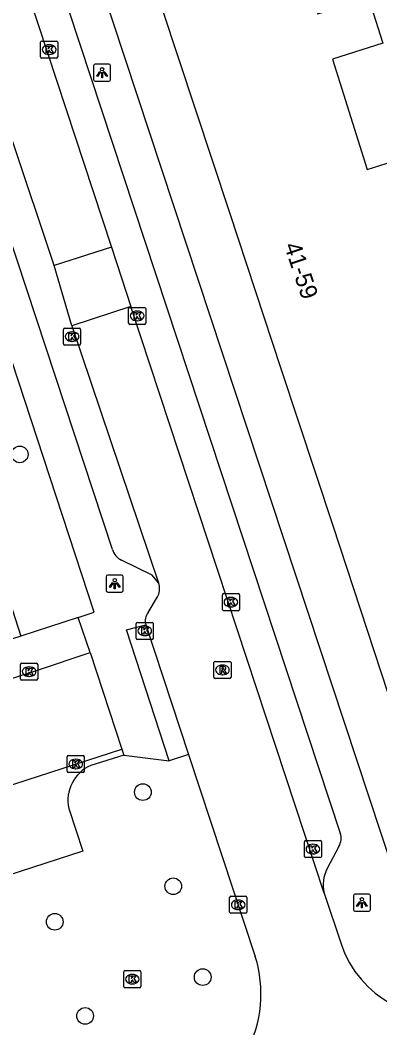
# Model space of a CAD drawing. Extents: x 159377 to 159983, y 382996 to 383595.
# Drawn here: x 159571.9 to 159592.9, y 383285.7 to 383344.8 of the extents above; entities that cross this region are included whole.
import ezdxf

# ---------------------------------------------------------------- set-up
doc = ezdxf.new("R2010")
doc.units = 0
for name, color, linetype in [('IMGEO_Boom', 7, 'Continuous'), ('IMGEO_Kolk', 7, 'Continuous'), ('IMGEO_Lichtpunt', 7, 'Continuous'), ('IMGEO_Pand', 7, 'Continuous'), ('IMGEO_Pand_nummerreeks', 7, 'Continuous'), ('IMGEO_Rijbaan_lokaal_open', 7, 'Continuous'), ('IMGEO_Rioolput', 7, 'Continuous'), ('IMGEO_Voetpad_open', 7, 'Continuous')]:
    doc.layers.add(name, color=color, linetype=linetype)

msp = doc.modelspace()

# ---------------------------------------------------------------- linework, layer by layer
at = {"layer": 'IMGEO_Boom'}
for centre in [(159571.842, 383319.363), (159579.055, 383299.558), (159580.837, 383294.038), (159573.891, 383291.953), (159582.558, 383288.709), (159575.673, 383286.434)]:
    msp.add_circle(centre, 0.489, dxfattribs=at)
at = {"layer": 'IMGEO_Kolk'}
for p, q in [((159573.064, 383342.675), (159573.064, 383343.527)), ((159573.139, 383343.601), (159573.991, 383343.601)), ((159574.065, 383343.527), (159574.065, 383342.675)), ((159573.552, 383343.381), (159573.577, 383343.381)), ((159573.991, 383342.601), (159573.139, 383342.601)), ((159573.575, 383342.821), (159573.55, 383342.821)), ((159578.219, 383327.058), (159578.219, 383327.91)), ((159578.294, 383327.984), (159579.146, 383327.984)), ((159578.707, 383327.764), (159578.732, 383327.764)), ((159579.22, 383327.91), (159579.22, 383327.058)), ((159579.146, 383326.984), (159578.294, 383326.984)), ((159578.73, 383327.204), (159578.705, 383327.204)), ((159574.405, 383325.842), (159574.405, 383326.694)), ((159574.48, 383326.768), (159575.332, 383326.768)), ((159574.893, 383326.548), (159574.918, 383326.548)), ((159575.406, 383326.694), (159575.406, 383325.842)), ((159575.332, 383325.768), (159574.48, 383325.768)), ((159574.916, 383325.988), (159574.891, 383325.988)), ((159583.712, 383310.272), (159583.712, 383311.124)), ((159583.787, 383311.198), (159584.639, 383311.198)), ((159584.2, 383310.978), (159584.225, 383310.978)), ((159584.713, 383311.124), (159584.713, 383310.272)), ((159584.223, 383310.418), (159584.198, 383310.418)), ((159584.639, 383310.198), (159583.787, 383310.198)), ((159578.666, 383308.588), (159578.666, 383309.44)), ((159578.741, 383309.514), (159579.593, 383309.514)), ((159579.154, 383309.294), (159579.179, 383309.294)), ((159579.667, 383309.44), (159579.667, 383308.588)), ((159579.177, 383308.734), (159579.152, 383308.734)), ((159579.593, 383308.514), (159578.741, 383308.514)), ((159571.891, 383306.197), (159571.891, 383307.049)), ((159571.966, 383307.123), (159572.818, 383307.123)), ((159572.379, 383306.903), (159572.404, 383306.903)), ((159572.892, 383307.049), (159572.892, 383306.197)), ((159572.402, 383306.343), (159572.377, 383306.343)), ((159572.818, 383306.123), (159571.966, 383306.123)), ((159574.624, 383300.779), (159574.624, 383301.631)), ((159574.699, 383301.705), (159575.551, 383301.705)), ((159575.625, 383301.631), (159575.625, 383300.779)), ((159575.135, 383300.925), (159575.11, 383300.925)), ((159575.112, 383301.485), (159575.137, 383301.485)), ((159575.551, 383300.705), (159574.699, 383300.705)), ((159588.514, 383295.791), (159588.514, 383296.643)), ((159588.589, 383296.717), (159589.441, 383296.717)), ((159589.002, 383296.497), (159589.027, 383296.497)), ((159589.515, 383296.643), (159589.515, 383295.791)), ((159589.441, 383295.717), (159588.589, 383295.717)), ((159589.025, 383295.937), (159589, 383295.937)), ((159584.137, 383292.525), (159584.137, 383293.377)), ((159584.212, 383293.451), (159585.064, 383293.451)), ((159584.625, 383293.231), (159584.65, 383293.231)), ((159585.138, 383293.377), (159585.138, 383292.525)), ((159584.648, 383292.671), (159584.623, 383292.671)), ((159585.064, 383292.451), (159584.212, 383292.451)), ((159578.01, 383289.089), (159578.862, 383289.089)), ((159577.935, 383288.163), (159577.935, 383289.015)), ((159578.423, 383288.869), (159578.448, 383288.869)), ((159578.936, 383289.015), (159578.936, 383288.163)), ((159578.862, 383288.089), (159578.01, 383288.089)), ((159578.446, 383288.309), (159578.421, 383288.309))]:
    msp.add_line(p, q, dxfattribs=at)
for points in [[(159573.064, 383342.675), (159573.064, 383343.527)], [(159573.139, 383343.601), (159573.991, 383343.601)], [(159574.065, 383343.527), (159574.065, 383342.675)], [(159573.385, 383343.301), (159573.508, 383343.301), (159573.508, 383343.15), (159573.638, 383343.301), (159573.802, 383343.301), (159573.656, 383343.15), (159573.809, 383342.901), (159573.657, 383342.901), (159573.572, 383343.065), (159573.508, 383342.998), (159573.508, 383342.901), (159573.385, 383342.901), (159573.385, 383343.301)], [(159573.991, 383342.601), (159573.139, 383342.601)], [(159578.219, 383327.058), (159578.219, 383327.91)], [(159578.294, 383327.984), (159579.146, 383327.984)], [(159578.54, 383327.684), (159578.663, 383327.684), (159578.663, 383327.533), (159578.793, 383327.684), (159578.957, 383327.684), (159578.811, 383327.533), (159578.964, 383327.284), (159578.812, 383327.284), (159578.727, 383327.448), (159578.663, 383327.381), (159578.663, 383327.284), (159578.54, 383327.284), (159578.54, 383327.684)], [(159579.22, 383327.91), (159579.22, 383327.058)], [(159579.146, 383326.984), (159578.294, 383326.984)], [(159574.405, 383325.842), (159574.405, 383326.694)], [(159574.48, 383326.768), (159575.332, 383326.768)], [(159574.726, 383326.468), (159574.849, 383326.468), (159574.849, 383326.317), (159574.979, 383326.468), (159575.143, 383326.468), (159574.997, 383326.317), (159575.15, 383326.068), (159574.998, 383326.068), (159574.913, 383326.232), (159574.849, 383326.165), (159574.849, 383326.068), (159574.726, 383326.068), (159574.726, 383326.468)], [(159575.406, 383326.694), (159575.406, 383325.842)], [(159575.332, 383325.768), (159574.48, 383325.768)], [(159583.712, 383310.272), (159583.712, 383311.124)], [(159583.787, 383311.198), (159584.639, 383311.198)], [(159584.713, 383311.124), (159584.713, 383310.272)], [(159584.033, 383310.898), (159584.156, 383310.898), (159584.156, 383310.747), (159584.286, 383310.898), (159584.45, 383310.898), (159584.304, 383310.747), (159584.457, 383310.498), (159584.305, 383310.498), (159584.22, 383310.662), (159584.156, 383310.595), (159584.156, 383310.498), (159584.033, 383310.498), (159584.033, 383310.898)], [(159584.639, 383310.198), (159583.787, 383310.198)], [(159578.666, 383308.588), (159578.666, 383309.44)], [(159578.741, 383309.514), (159579.593, 383309.514)], [(159578.987, 383309.214), (159579.11, 383309.214), (159579.11, 383309.063), (159579.24, 383309.214), (159579.404, 383309.214), (159579.258, 383309.063), (159579.411, 383308.814), (159579.259, 383308.814), (159579.174, 383308.978), (159579.11, 383308.911), (159579.11, 383308.814), (159578.987, 383308.814), (159578.987, 383309.214)], [(159579.667, 383309.44), (159579.667, 383308.588)], [(159579.593, 383308.514), (159578.741, 383308.514)], [(159571.891, 383306.197), (159571.891, 383307.049)], [(159571.966, 383307.123), (159572.818, 383307.123)], [(159572.212, 383306.823), (159572.335, 383306.823), (159572.335, 383306.672), (159572.465, 383306.823), (159572.629, 383306.823), (159572.483, 383306.672), (159572.636, 383306.423), (159572.484, 383306.423), (159572.399, 383306.587), (159572.335, 383306.52), (159572.335, 383306.423), (159572.212, 383306.423), (159572.212, 383306.823)], [(159572.892, 383307.049), (159572.892, 383306.197)], [(159572.818, 383306.123), (159571.966, 383306.123)], [(159574.624, 383300.779), (159574.624, 383301.631)], [(159574.699, 383301.705), (159575.551, 383301.705)], [(159575.625, 383301.631), (159575.625, 383300.779)], [(159574.945, 383301.405), (159575.068, 383301.405), (159575.068, 383301.254), (159575.198, 383301.405), (159575.362, 383301.405), (159575.216, 383301.254), (159575.369, 383301.005), (159575.217, 383301.005), (159575.132, 383301.169), (159575.068, 383301.102), (159575.068, 383301.005), (159574.945, 383301.005), (159574.945, 383301.405)], [(159575.551, 383300.705), (159574.699, 383300.705)], [(159588.514, 383295.791), (159588.514, 383296.643)], [(159588.589, 383296.717), (159589.441, 383296.717)], [(159588.835, 383296.417), (159588.958, 383296.417), (159588.958, 383296.266), (159589.088, 383296.417), (159589.252, 383296.417), (159589.106, 383296.266), (159589.259, 383296.017), (159589.107, 383296.017), (159589.022, 383296.181), (159588.958, 383296.114), (159588.958, 383296.017), (159588.835, 383296.017), (159588.835, 383296.417)], [(159589.515, 383296.643), (159589.515, 383295.791)], [(159589.441, 383295.717), (159588.589, 383295.717)], [(159584.137, 383292.525), (159584.137, 383293.377)], [(159584.212, 383293.451), (159585.064, 383293.451)], [(159585.138, 383293.377), (159585.138, 383292.525)], [(159584.458, 383293.151), (159584.581, 383293.151), (159584.581, 383293), (159584.711, 383293.151), (159584.875, 383293.151), (159584.729, 383293), (159584.882, 383292.751), (159584.73, 383292.751), (159584.645, 383292.915), (159584.581, 383292.848), (159584.581, 383292.751), (159584.458, 383292.751), (159584.458, 383293.151)], [(159585.064, 383292.451), (159584.212, 383292.451)], [(159578.01, 383289.089), (159578.862, 383289.089)], [(159577.935, 383288.163), (159577.935, 383289.015)], [(159578.256, 383288.789), (159578.379, 383288.789), (159578.379, 383288.638), (159578.509, 383288.789), (159578.673, 383288.789), (159578.527, 383288.638), (159578.68, 383288.389), (159578.528, 383288.389), (159578.443, 383288.553), (159578.379, 383288.486), (159578.379, 383288.389), (159578.256, 383288.389), (159578.256, 383288.789)], [(159578.936, 383289.015), (159578.936, 383288.163)], [(159578.862, 383288.089), (159578.01, 383288.089)]]:
    msp.add_lwpolyline(points, dxfattribs=at)
for centre, start, end in [((159573.141, 383343.525), 91.55205, 178.44795), ((159573.141, 383343.525), 91.55205, 178.44795), ((159573.989, 383343.525), 1.55205, 88.44795), ((159573.989, 383343.525), 1.55205, 88.44795), ((159573.141, 383342.677), 181.55205, 268.44795), ((159573.141, 383342.677), 181.55205, 268.44795), ((159573.989, 383342.677), 271.55205, 358.44795), ((159573.989, 383342.677), 271.55205, 358.44795), ((159578.296, 383327.908), 91.55205, 178.44795), ((159578.296, 383327.908), 91.55205, 178.44795), ((159579.144, 383327.908), 1.55205, 88.44795), ((159579.144, 383327.908), 1.55205, 88.44795), ((159578.296, 383327.06), 181.55205, 268.44795), ((159578.296, 383327.06), 181.55205, 268.44795), ((159579.144, 383327.06), 271.55205, 358.44795), ((159579.144, 383327.06), 271.55205, 358.44795), ((159574.482, 383326.692), 91.55205, 178.44795), ((159574.482, 383326.692), 91.55205, 178.44795), ((159575.33, 383326.692), 1.55205, 88.44795), ((159575.33, 383326.692), 1.55205, 88.44795), ((159574.482, 383325.844), 181.55205, 268.44795), ((159574.482, 383325.844), 181.55205, 268.44795), ((159575.33, 383325.844), 271.55205, 358.44795), ((159575.33, 383325.844), 271.55205, 358.44795), ((159583.789, 383311.122), 91.55205, 178.44795), ((159583.789, 383311.122), 91.55205, 178.44795), ((159584.637, 383311.122), 1.55205, 88.44795), ((159584.637, 383311.122), 1.55205, 88.44795), ((159583.789, 383310.274), 181.55205, 268.44795), ((159583.789, 383310.274), 181.55205, 268.44795), ((159584.637, 383310.274), 271.55205, 358.44795), ((159584.637, 383310.274), 271.55205, 358.44795), ((159578.743, 383309.438), 91.55205, 178.44795), ((159578.743, 383309.438), 91.55205, 178.44795), ((159579.591, 383309.438), 1.55205, 88.44795), ((159579.591, 383309.438), 1.55205, 88.44795), ((159578.743, 383308.59), 181.55205, 268.44795), ((159578.743, 383308.59), 181.55205, 268.44795), ((159579.591, 383308.59), 271.55205, 358.44795), ((159579.591, 383308.59), 271.55205, 358.44795), ((159571.968, 383307.047), 91.55205, 178.44795), ((159571.968, 383307.047), 91.55205, 178.44795), ((159572.816, 383307.047), 1.55205, 88.44795), ((159572.816, 383307.047), 1.55205, 88.44795), ((159571.968, 383306.199), 181.55205, 268.44795), ((159571.968, 383306.199), 181.55205, 268.44795), ((159572.816, 383306.199), 271.55205, 358.44795), ((159572.816, 383306.199), 271.55205, 358.44795), ((159574.701, 383301.629), 91.55205, 178.44795), ((159574.701, 383301.629), 91.55205, 178.44795), ((159575.549, 383301.629), 1.55205, 88.44795), ((159575.549, 383301.629), 1.55205, 88.44795), ((159574.701, 383300.781), 181.55205, 268.44795), ((159574.701, 383300.781), 181.55205, 268.44795), ((159575.549, 383300.781), 271.55205, 358.44795), ((159575.549, 383300.781), 271.55205, 358.44795), ((159588.591, 383296.641), 91.55205, 178.44795), ((159588.591, 383296.641), 91.55205, 178.44795), ((159589.439, 383296.641), 1.55205, 88.44795), ((159589.439, 383296.641), 1.55205, 88.44795), ((159588.591, 383295.793), 181.55205, 268.44795), ((159588.591, 383295.793), 181.55205, 268.44795), ((159589.439, 383295.793), 271.55205, 358.44795), ((159589.439, 383295.793), 271.55205, 358.44795), ((159584.214, 383293.375), 91.55205, 178.44795), ((159584.214, 383293.375), 91.55205, 178.44795), ((159585.062, 383293.375), 1.55205, 88.44795), ((159585.062, 383293.375), 1.55205, 88.44795), ((159584.214, 383292.527), 181.55205, 268.44795), ((159584.214, 383292.527), 181.55205, 268.44795), ((159585.062, 383292.527), 271.55205, 358.44795), ((159585.062, 383292.527), 271.55205, 358.44795), ((159578.012, 383289.013), 91.55205, 178.44795), ((159578.012, 383289.013), 91.55205, 178.44795), ((159578.86, 383289.013), 1.55205, 88.44795), ((159578.86, 383289.013), 1.55205, 88.44795), ((159578.012, 383288.165), 181.55205, 268.44795), ((159578.012, 383288.165), 181.55205, 268.44795), ((159578.86, 383288.165), 271.55205, 358.44795), ((159578.86, 383288.165), 271.55205, 358.44795)]:
    msp.add_arc(centre, 0.0765, start, end, dxfattribs=at)
for centre, major_axis, ratio, start_param, end_param in [((159573.551, 383343.101), (-0.387, 0.002), 0.722429, 4.712389, 7.853982), ((159573.576, 383343.101), (-0.39, 0.002), 0.717154, 1.570796, 4.712389), ((159578.706, 383327.484), (-0.387, 0.002), 0.722429, 4.712389, 7.853982), ((159578.731, 383327.484), (-0.39, 0.002), 0.717154, 1.570796, 4.712389), ((159574.892, 383326.268), (-0.387, 0.002), 0.722429, 4.712389, 7.853982), ((159574.917, 383326.268), (-0.39, 0.002), 0.717154, 1.570796, 4.712389), ((159584.199, 383310.698), (-0.387, 0.002), 0.722429, 4.712389, 7.853982), ((159584.224, 383310.698), (-0.39, 0.002), 0.717154, 1.570796, 4.712389), ((159579.153, 383309.014), (-0.387, 0.002), 0.722429, 4.712389, 7.853982), ((159579.178, 383309.014), (-0.39, 0.002), 0.717154, 1.570796, 4.712389), ((159572.378, 383306.623), (-0.387, 0.002), 0.722429, 4.712389, 7.853982), ((159572.403, 383306.623), (-0.39, 0.002), 0.717154, 1.570796, 4.712389), ((159575.111, 383301.205), (-0.387, 0.002), 0.722429, 4.712389, 7.853982), ((159575.136, 383301.205), (-0.39, 0.002), 0.717154, 1.570796, 4.712389), ((159589.001, 383296.217), (-0.387, 0.002), 0.722429, 4.712389, 7.853982), ((159589.026, 383296.217), (-0.39, 0.002), 0.717154, 1.570796, 4.712389), ((159584.624, 383292.951), (-0.387, 0.002), 0.722429, 4.712389, 7.853982), ((159584.649, 383292.951), (-0.39, 0.002), 0.717154, 1.570796, 4.712389), ((159578.422, 383288.589), (-0.387, 0.002), 0.722429, 4.712389, 7.853982), ((159578.447, 383288.589), (-0.39, 0.002), 0.717154, 1.570796, 4.712389)]:
    msp.add_ellipse(centre, major_axis=major_axis, ratio=ratio, start_param=start_param, end_param=end_param, dxfattribs=at)
at = {"layer": 'IMGEO_Lichtpunt'}
for p, q in [((159576.165, 383342.151), (159576.165, 383341.344)), ((159576.165, 383342.151), (159576.165, 383341.344)), ((159577.067, 383342.246), (159576.259, 383342.246)), ((159577.067, 383342.246), (159576.259, 383342.246)), ((159577.161, 383341.344), (159577.161, 383342.151)), ((159577.161, 383341.344), (159577.161, 383342.151)), ((159576.259, 383341.25), (159577.067, 383341.25)), ((159576.259, 383341.25), (159577.067, 383341.25)), ((159576.906, 383312.188), (159576.906, 383311.381)), ((159576.906, 383312.188), (159576.906, 383311.381)), ((159577.808, 383312.283), (159577, 383312.283)), ((159577.808, 383312.283), (159577, 383312.283)), ((159577.902, 383311.381), (159577.902, 383312.188)), ((159577.902, 383311.381), (159577.902, 383312.188)), ((159577, 383311.287), (159577.808, 383311.287)), ((159577, 383311.287), (159577.808, 383311.287)), ((159591.385, 383293.478), (159591.385, 383292.671)), ((159591.385, 383293.478), (159591.385, 383292.671)), ((159592.287, 383293.573), (159591.479, 383293.573)), ((159592.287, 383293.573), (159591.479, 383293.573)), ((159592.381, 383292.671), (159592.381, 383293.478)), ((159592.381, 383292.671), (159592.381, 383293.478)), ((159591.479, 383292.577), (159592.287, 383292.577)), ((159591.479, 383292.577), (159592.287, 383292.577))]:
    msp.add_line(p, q, dxfattribs=at)
for points in [[(159576.539, 383341.815), (159576.578, 383341.787), (159576.39, 383341.525), (159576.352, 383341.552), (159576.539, 383341.815)], [(159576.641, 383341.767), (159576.688, 383341.767), (159576.688, 383341.445), (159576.641, 383341.445), (159576.641, 383341.767)], [(159576.751, 383341.787), (159576.789, 383341.814), (159576.976, 383341.552), (159576.937, 383341.524), (159576.751, 383341.787)], [(159577.28, 383311.852), (159577.319, 383311.824), (159577.131, 383311.562), (159577.093, 383311.589), (159577.28, 383311.852)], [(159577.382, 383311.804), (159577.429, 383311.804), (159577.429, 383311.482), (159577.382, 383311.482), (159577.382, 383311.804)], [(159577.492, 383311.824), (159577.53, 383311.851), (159577.717, 383311.589), (159577.678, 383311.561), (159577.492, 383311.824)], [(159591.759, 383293.142), (159591.798, 383293.114), (159591.61, 383292.852), (159591.572, 383292.879), (159591.759, 383293.142)], [(159591.861, 383293.094), (159591.908, 383293.094), (159591.908, 383292.772), (159591.861, 383292.772), (159591.861, 383293.094)], [(159591.971, 383293.114), (159592.009, 383293.141), (159592.196, 383292.879), (159592.157, 383292.851), (159591.971, 383293.114)]]:
    msp.add_lwpolyline(points, dxfattribs=at)
for centre in [(159576.664, 383341.949), (159577.405, 383311.986), (159591.884, 383293.276)]:
    msp.add_circle(centre, 0.0994, dxfattribs=at)
for centre, start, end in [((159576.259, 383342.151), 90, 180), ((159576.259, 383342.151), 90, 180), ((159577.067, 383342.151), 0, 90), ((159577.067, 383342.151), 0, 90), ((159576.259, 383341.344), 180, 270), ((159576.259, 383341.344), 180, 270), ((159577.067, 383341.344), 270, 0), ((159577.067, 383341.344), 270, 360), ((159577, 383312.188), 90, 180), ((159577, 383312.188), 90, 180), ((159577.808, 383312.188), 0, 90), ((159577.808, 383312.188), 0, 90), ((159577, 383311.381), 180, 270), ((159577, 383311.381), 180, 270), ((159577.808, 383311.381), 270, 0), ((159577.808, 383311.381), 270, 360), ((159591.479, 383293.478), 90, 180), ((159591.479, 383293.478), 90, 180), ((159592.287, 383293.478), 0, 90), ((159592.287, 383293.478), 0, 90), ((159591.479, 383292.671), 180, 270), ((159591.479, 383292.671), 180, 270), ((159592.287, 383292.671), 270, 0), ((159592.287, 383292.671), 270, 360)]:
    msp.add_arc(centre, 0.0946, start, end, dxfattribs=at)
at = {"layer": 'IMGEO_Pand'}
for points in [[(159588.044, 383354.159), (159588.744, 383351.948), (159587.314, 383351.496), (159589.306, 383345.204), (159592.262, 383346.14), (159593.108, 383343.471), (159590.153, 383342.536), (159592.2, 383336.073), (159595.156, 383337.009)], [(159611.905, 383311.499), (159602.997, 383308.531), (159593.432, 383305.343), (159590.192, 383315.167), (159587.154, 383324.378), (159584.139, 383333.52), (159581.139, 383342.617), (159578.288, 383351.261)], [(159569.263, 383316.872), (159571.909, 383308.713)], [(159571.909, 383308.713), (159566.56, 383306.979)]]:
    msp.add_lwpolyline(points, dxfattribs=at)
at = {"layer": 'IMGEO_Rijbaan_lokaal_open'}
for points in [[(159567.018, 383362.457), (159577.211, 383331.524)], [(159573.85, 383330.431), (159571.401, 383337.809)], [(159577.211, 383331.524), (159573.85, 383330.431)], [(159577.211, 383331.524), (159578.358, 383328.035)], [(159574.888, 383326.906), (159573.85, 383330.431)], [(159578.358, 383328.035), (159574.888, 383326.906)], [(159589.681, 383293.637), (159578.358, 383328.035)], [(159574.888, 383326.906), (159579.969, 383311.833)], [(159580.004, 383311.729), (159579.969, 383311.833)], [(159579.367, 383310.098), (159579.909, 383311.002)], [(159580.597, 383301.394), (159578.087, 383309.067), (159579.223, 383309.377)], [(159579.223, 383309.377), (159581.731, 383301.756)], [(159544.818, 383297.679), (159572.877, 383306.719), (159575.958, 383307.741)], [(159575.958, 383307.741), (159577.82, 383302.082)], [(159554.057, 383294.368), (159577.82, 383302.082)], [(159581.731, 383301.756), (159580.597, 383301.394)], [(159581.731, 383301.756), (159585.641, 383289.914)], [(159589.681, 383293.637), (159590.665, 383290.654)]]:
    msp.add_lwpolyline(points, dxfattribs=at)
for centre, radius, start, end in [((159579.094, 383311.478), 0.944, 329.69692, 15.41331), ((159580.007, 383309.595), 0.814, 141.8515, 195.5592), ((159596.639, 383292.667), 6.304, 198.62049, 284.29088), ((159578.704, 383287.742), 7.269, 286.2109, 17.3819)]:
    msp.add_arc(centre, radius, start, end, dxfattribs=at)
at = {"layer": 'IMGEO_Rioolput'}
for p, q in [((159583.217, 383306.298), (159583.217, 383307.15)), ((159583.292, 383307.224), (159584.144, 383307.224)), ((159583.705, 383307.004), (159583.73, 383307.004)), ((159584.218, 383307.15), (159584.218, 383306.298)), ((159584.144, 383306.224), (159583.292, 383306.224)), ((159583.728, 383306.444), (159583.703, 383306.444))]:
    msp.add_line(p, q, dxfattribs=at)
for points in [[(159583.217, 383306.298), (159583.217, 383307.15)], [(159583.292, 383307.224), (159584.144, 383307.224)], [(159583.806, 383306.922), (159583.554, 383306.924), (159583.554, 383306.524)], [(159583.732, 383306.843), (159583.678, 383306.843), (159583.678, 383306.762)], [(159584.218, 383307.15), (159584.218, 383306.298)], [(159584.144, 383306.224), (159583.292, 383306.224)], [(159583.554, 383306.524), (159583.678, 383306.524), (159583.678, 383306.686), (159583.689, 383306.686)], [(159583.678, 383306.762), (159583.73, 383306.762)], [(159583.736, 383306.657), (159583.807, 383306.524), (159583.947, 383306.524), (159583.882, 383306.65)]]:
    msp.add_lwpolyline(points, dxfattribs=at)
for centre, radius, start, end in [((159583.294, 383307.148), 0.0765, 91.55205, 178.44795), ((159583.294, 383307.148), 0.0765, 91.55205, 178.44795), ((159583.738, 383306.747), 0.0964, 77.00612, 93.18647), ((159583.752, 383306.804), 0.0378, 276.66336, 79.67722), ((159583.805, 383306.812), 0.109, 350.36119, 89.41601), ((159584.142, 383307.148), 0.0765, 1.55205, 88.44795), ((159584.142, 383307.148), 0.0765, 1.55205, 88.44795), ((159583.294, 383306.3), 0.0765, 181.55205, 268.44795), ((159583.294, 383306.3), 0.0765, 181.55205, 268.44795), ((159583.688, 383306.633), 0.0533, 26.02933, 88.69889), ((159583.714, 383306.951), 0.19, 274.7715, 282.96867), ((159583.803, 383306.812), 0.112, 277.58423, 350.98172), ((159583.787, 383306.597), 0.108, 29.51342, 73.79051), ((159584.142, 383306.3), 0.0765, 271.55205, 358.44795), ((159584.142, 383306.3), 0.0765, 271.55205, 358.44795)]:
    msp.add_arc(centre, radius, start, end, dxfattribs=at)
for centre, major_axis, ratio, start_param, end_param in [((159583.704, 383306.724), (-0.387, 0.002), 0.722429, 4.712389, 7.853982), ((159583.729, 383306.724), (-0.39, 0.002), 0.717154, 1.570796, 4.712389)]:
    msp.add_ellipse(centre, major_axis=major_axis, ratio=ratio, start_param=start_param, end_param=end_param, dxfattribs=at)
at = {"layer": 'IMGEO_Voetpad_open'}
for points in [[(159551.811, 383414.828), (159590.619, 383297.142)], [(159573.702, 383355.642), (159595.869, 383288.453), (159597.121, 383288.896)], [(159577.282, 383313.777), (159570.55, 383334.129)], [(159575.265, 383309.805), (159576.204, 383310.11), (159570.274, 383328.182)], [(159579.969, 383311.833), (159579.599, 383312.276), (159577.808, 383313.161)], [(159575.265, 383309.805), (159571.909, 383308.713)], [(159575.958, 383307.741), (159575.265, 383309.805)], [(159577.82, 383302.082), (159577.937, 383301.725)], [(159577.937, 383301.725), (159576.008, 383301.124)], [(159577.937, 383301.725), (159580.597, 383301.394)], [(159574.713, 383298.601), (159575.546, 383296.103), (159568.834, 383293.928)], [(159590.537, 383296.377), (159589.846, 383295.075)]]:
    msp.add_lwpolyline(points, dxfattribs=at)
for centre, radius, start, end in [((159578.198, 383314.026), 0.949, 195.22518, 245.76259), ((159576.91, 383299.067), 2.246, 113.67635, 191.9828), ((159589.727, 383296.851), 0.939, 329.69088, 18.07282), ((159591.619, 383294.143), 2.003, 152.2707, 194.638)]:
    msp.add_arc(centre, radius, start, end, dxfattribs=at)

# ---------------------------------------------------------------- texts
at = {"layer": 'IMGEO_Pand_nummerreeks'}
msp.add_text('41-59', height=1, rotation=288.49487, dxfattribs=at).set_placement((159587.315, 383331.615))

doc.saveas('drawing.dxf')
